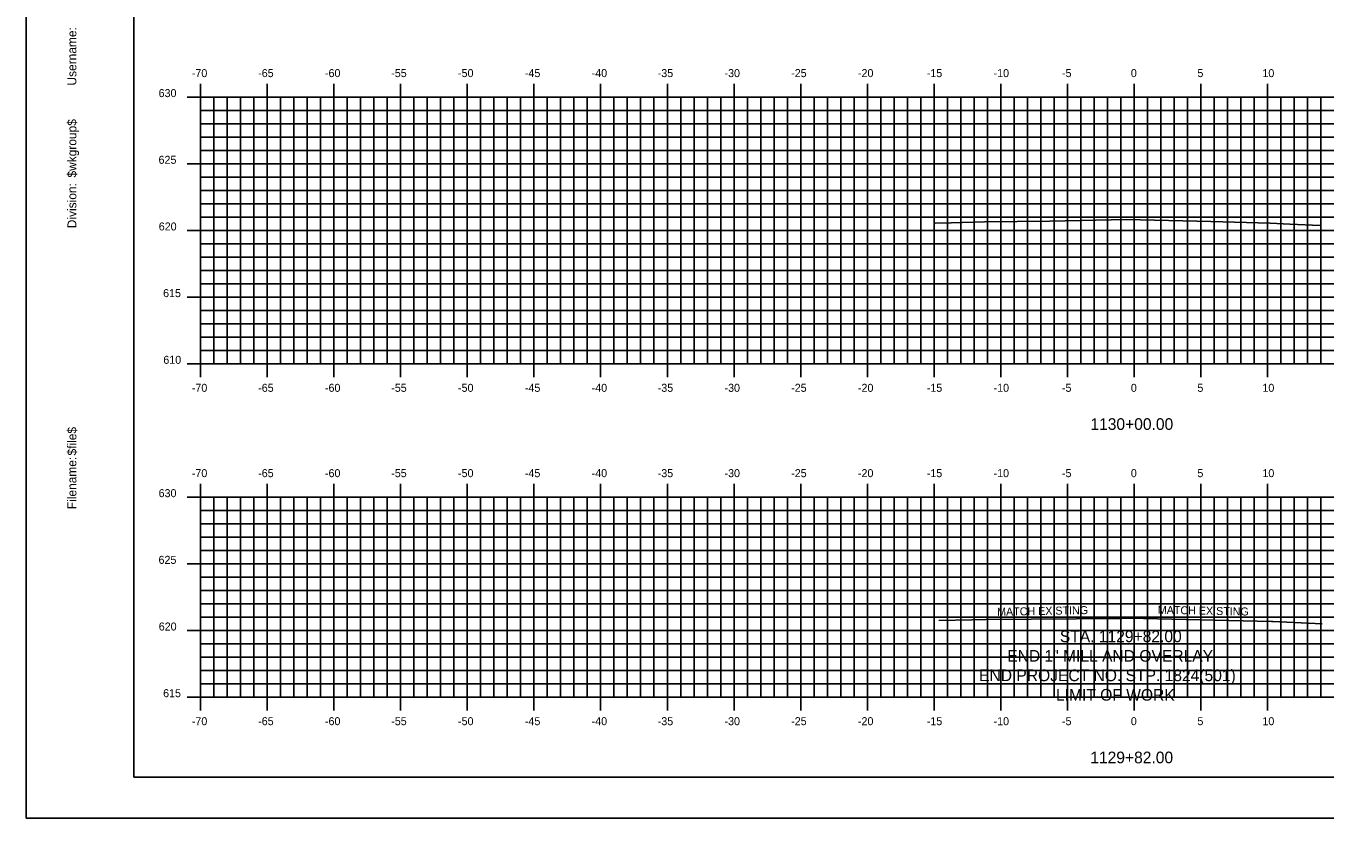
# Model space of a CAD drawing. Extents: x 1089609 to 1089779, y 779716 to 779826.
# Drawn here: x 1089609.1 to 1089706.6, y 779715.6 to 779775 of the extents above; entities that cross this region are included whole.
import ezdxf

# ---------------------------------------------------------------- set-up
doc = ezdxf.new("R2010")
doc.units = 0
for name, color, linetype in [('ANNOTATION', 7, 'Continuous'), ('BORDER', 7, 'Continuous'), ('H_V ANNOTATION', 7, 'Continuous'), ('MAJOR', 7, 'Continuous'), ('MINOR', 7, 'Continuous'), ('PLOT BOUNDARY', 7, 'Continuous'), ('S_Roadway_Centerline', 7, 'Continuous')]:
    doc.layers.add(name, color=color, linetype=linetype)

msp = doc.modelspace()

# ---------------------------------------------------------------- linework, layer by layer
at = {"layer": 'BORDER'}
msp.add_lwpolyline([(1089617.187, 779718.706), (1089777.187, 779718.706), (1089777.187, 779823.706), (1089617.187, 779823.706)], close=True, dxfattribs=at)
at = {"layer": 'MAJOR'}
for p, q in [((1089622.187, 779770.708), (1089622.187, 779769.706)), ((1089627.187, 779770.708), (1089627.187, 779769.706)), ((1089632.187, 779770.708), (1089632.187, 779769.706)), ((1089637.187, 779770.708), (1089637.187, 779769.706)), ((1089642.187, 779770.708), (1089642.187, 779769.706)), ((1089647.187, 779770.708), (1089647.187, 779769.706)), ((1089652.187, 779770.708), (1089652.187, 779769.706)), ((1089657.187, 779770.708), (1089657.187, 779769.706)), ((1089662.187, 779770.708), (1089662.187, 779769.706)), ((1089667.187, 779770.708), (1089667.187, 779769.706)), ((1089672.187, 779770.708), (1089672.187, 779769.706)), ((1089677.187, 779770.708), (1089677.187, 779769.706)), ((1089682.187, 779770.708), (1089682.187, 779769.706)), ((1089687.187, 779770.708), (1089687.187, 779769.706)), ((1089692.187, 779770.708), (1089692.187, 779769.706)), ((1089697.187, 779770.708), (1089697.187, 779769.706)), ((1089702.187, 779770.708), (1089702.187, 779769.706)), ((1089621.185, 779769.706), (1089622.187, 779769.706)), ((1089622.187, 779769.706), (1089762.187, 779769.706)), ((1089622.187, 779749.706), (1089622.187, 779769.706)), ((1089622.187, 779749.706), (1089622.187, 779769.706)), ((1089622.187, 779769.706), (1089762.187, 779769.706)), ((1089627.187, 779749.706), (1089627.187, 779769.706)), ((1089632.187, 779749.706), (1089632.187, 779769.706)), ((1089637.187, 779749.706), (1089637.187, 779769.706)), ((1089642.187, 779749.706), (1089642.187, 779769.706)), ((1089647.187, 779749.706), (1089647.187, 779769.706)), ((1089652.187, 779749.706), (1089652.187, 779769.706)), ((1089657.187, 779749.706), (1089657.187, 779769.706)), ((1089662.187, 779749.706), (1089662.187, 779769.706)), ((1089667.187, 779749.706), (1089667.187, 779769.706)), ((1089672.187, 779749.706), (1089672.187, 779769.706)), ((1089677.187, 779749.706), (1089677.187, 779769.706)), ((1089682.187, 779749.706), (1089682.187, 779769.706)), ((1089687.187, 779749.706), (1089687.187, 779769.706)), ((1089692.187, 779749.706), (1089692.187, 779769.706)), ((1089697.187, 779749.706), (1089697.187, 779769.706)), ((1089702.187, 779749.706), (1089702.187, 779769.706)), ((1089621.185, 779764.706), (1089622.187, 779764.706)), ((1089622.187, 779764.706), (1089762.187, 779764.706)), ((1089621.185, 779759.706), (1089622.187, 779759.706)), ((1089622.187, 779759.706), (1089762.187, 779759.706)), ((1089621.185, 779754.706), (1089622.187, 779754.706)), ((1089622.187, 779754.706), (1089762.187, 779754.706)), ((1089621.185, 779749.706), (1089622.187, 779749.706)), ((1089622.187, 779749.706), (1089762.187, 779749.706)), ((1089622.187, 779749.706), (1089762.187, 779749.706)), ((1089622.187, 779748.704), (1089622.187, 779749.706)), ((1089627.187, 779748.704), (1089627.187, 779749.706)), ((1089632.187, 779748.704), (1089632.187, 779749.706)), ((1089637.187, 779748.704), (1089637.187, 779749.706)), ((1089642.187, 779748.704), (1089642.187, 779749.706)), ((1089647.187, 779748.704), (1089647.187, 779749.706)), ((1089652.187, 779748.704), (1089652.187, 779749.706)), ((1089657.187, 779748.704), (1089657.187, 779749.706)), ((1089662.187, 779748.704), (1089662.187, 779749.706)), ((1089667.187, 779748.704), (1089667.187, 779749.706)), ((1089672.187, 779748.704), (1089672.187, 779749.706)), ((1089677.187, 779748.704), (1089677.187, 779749.706)), ((1089682.187, 779748.704), (1089682.187, 779749.706)), ((1089687.187, 779748.704), (1089687.187, 779749.706)), ((1089692.187, 779748.704), (1089692.187, 779749.706)), ((1089697.187, 779748.704), (1089697.187, 779749.706)), ((1089702.187, 779748.704), (1089702.187, 779749.706)), ((1089622.187, 779740.708), (1089622.187, 779739.706)), ((1089627.187, 779740.708), (1089627.187, 779739.706)), ((1089632.187, 779740.708), (1089632.187, 779739.706)), ((1089637.187, 779740.708), (1089637.187, 779739.706)), ((1089642.187, 779740.708), (1089642.187, 779739.706)), ((1089647.187, 779740.708), (1089647.187, 779739.706)), ((1089652.187, 779740.708), (1089652.187, 779739.706)), ((1089657.187, 779740.708), (1089657.187, 779739.706)), ((1089662.187, 779740.708), (1089662.187, 779739.706)), ((1089667.187, 779740.708), (1089667.187, 779739.706)), ((1089672.187, 779740.708), (1089672.187, 779739.706)), ((1089677.187, 779740.708), (1089677.187, 779739.706)), ((1089682.187, 779740.708), (1089682.187, 779739.706)), ((1089687.187, 779740.708), (1089687.187, 779739.706)), ((1089692.187, 779740.708), (1089692.187, 779739.706)), ((1089697.187, 779740.708), (1089697.187, 779739.706)), ((1089702.187, 779740.708), (1089702.187, 779739.706)), ((1089621.185, 779739.706), (1089622.187, 779739.706)), ((1089622.187, 779739.706), (1089762.187, 779739.706)), ((1089622.187, 779724.706), (1089622.187, 779739.706)), ((1089622.187, 779724.706), (1089622.187, 779739.706)), ((1089622.187, 779739.706), (1089762.187, 779739.706)), ((1089627.187, 779724.706), (1089627.187, 779739.706)), ((1089632.187, 779724.706), (1089632.187, 779739.706)), ((1089637.187, 779724.706), (1089637.187, 779739.706)), ((1089642.187, 779724.706), (1089642.187, 779739.706)), ((1089647.187, 779724.706), (1089647.187, 779739.706)), ((1089652.187, 779724.706), (1089652.187, 779739.706)), ((1089657.187, 779724.706), (1089657.187, 779739.706)), ((1089662.187, 779724.706), (1089662.187, 779739.706)), ((1089667.187, 779724.706), (1089667.187, 779739.706)), ((1089672.187, 779724.706), (1089672.187, 779739.706)), ((1089677.187, 779724.706), (1089677.187, 779739.706)), ((1089682.187, 779724.706), (1089682.187, 779739.706)), ((1089687.187, 779724.706), (1089687.187, 779739.706)), ((1089692.187, 779724.706), (1089692.187, 779739.706)), ((1089697.187, 779724.706), (1089697.187, 779739.706)), ((1089702.187, 779724.706), (1089702.187, 779739.706)), ((1089621.185, 779734.706), (1089622.187, 779734.706)), ((1089622.187, 779734.706), (1089762.187, 779734.706)), ((1089621.185, 779729.706), (1089622.187, 779729.706)), ((1089622.187, 779729.706), (1089762.187, 779729.706)), ((1089621.185, 779724.706), (1089622.187, 779724.706)), ((1089622.187, 779724.706), (1089762.187, 779724.706)), ((1089622.187, 779724.706), (1089762.187, 779724.706)), ((1089622.187, 779723.704), (1089622.187, 779724.706)), ((1089627.187, 779723.704), (1089627.187, 779724.706)), ((1089632.187, 779723.704), (1089632.187, 779724.706)), ((1089637.187, 779723.704), (1089637.187, 779724.706)), ((1089642.187, 779723.704), (1089642.187, 779724.706)), ((1089647.187, 779723.704), (1089647.187, 779724.706)), ((1089652.187, 779723.704), (1089652.187, 779724.706)), ((1089657.187, 779723.704), (1089657.187, 779724.706)), ((1089662.187, 779723.704), (1089662.187, 779724.706)), ((1089667.187, 779723.704), (1089667.187, 779724.706)), ((1089672.187, 779723.704), (1089672.187, 779724.706)), ((1089677.187, 779723.704), (1089677.187, 779724.706)), ((1089682.187, 779723.704), (1089682.187, 779724.706)), ((1089687.187, 779723.704), (1089687.187, 779724.706)), ((1089692.187, 779723.704), (1089692.187, 779724.706)), ((1089697.187, 779723.704), (1089697.187, 779724.706)), ((1089702.187, 779723.704), (1089702.187, 779724.706))]:
    msp.add_line(p, q, dxfattribs=at)
at = {"layer": 'MINOR'}
for p, q in [((1089623.187, 779749.706), (1089623.187, 779769.706)), ((1089624.187, 779749.706), (1089624.187, 779769.706)), ((1089625.187, 779749.706), (1089625.187, 779769.706)), ((1089626.187, 779749.706), (1089626.187, 779769.706)), ((1089628.187, 779749.706), (1089628.187, 779769.706)), ((1089629.187, 779749.706), (1089629.187, 779769.706)), ((1089630.187, 779749.706), (1089630.187, 779769.706)), ((1089631.187, 779749.706), (1089631.187, 779769.706)), ((1089633.187, 779749.706), (1089633.187, 779769.706)), ((1089634.187, 779749.706), (1089634.187, 779769.706)), ((1089635.187, 779749.706), (1089635.187, 779769.706)), ((1089636.187, 779749.706), (1089636.187, 779769.706)), ((1089638.187, 779749.706), (1089638.187, 779769.706)), ((1089639.187, 779749.706), (1089639.187, 779769.706)), ((1089640.187, 779749.706), (1089640.187, 779769.706)), ((1089641.187, 779749.706), (1089641.187, 779769.706)), ((1089643.187, 779749.706), (1089643.187, 779769.706)), ((1089644.187, 779749.706), (1089644.187, 779769.706)), ((1089645.187, 779749.706), (1089645.187, 779769.706)), ((1089646.187, 779749.706), (1089646.187, 779769.706)), ((1089648.187, 779749.706), (1089648.187, 779769.706)), ((1089649.187, 779749.706), (1089649.187, 779769.706)), ((1089650.187, 779749.706), (1089650.187, 779769.706)), ((1089651.187, 779749.706), (1089651.187, 779769.706)), ((1089653.187, 779749.706), (1089653.187, 779769.706)), ((1089654.187, 779749.706), (1089654.187, 779769.706)), ((1089655.187, 779749.706), (1089655.187, 779769.706)), ((1089656.187, 779749.706), (1089656.187, 779769.706)), ((1089658.187, 779749.706), (1089658.187, 779769.706)), ((1089659.187, 779749.706), (1089659.187, 779769.706)), ((1089660.187, 779749.706), (1089660.187, 779769.706)), ((1089661.187, 779749.706), (1089661.187, 779769.706)), ((1089663.187, 779749.706), (1089663.187, 779769.706)), ((1089664.187, 779749.706), (1089664.187, 779769.706)), ((1089665.187, 779749.706), (1089665.187, 779769.706)), ((1089666.187, 779749.706), (1089666.187, 779769.706)), ((1089668.187, 779749.706), (1089668.187, 779769.706)), ((1089669.187, 779749.706), (1089669.187, 779769.706)), ((1089670.187, 779749.706), (1089670.187, 779769.706)), ((1089671.187, 779749.706), (1089671.187, 779769.706)), ((1089673.187, 779749.706), (1089673.187, 779769.706)), ((1089674.187, 779749.706), (1089674.187, 779769.706)), ((1089675.187, 779749.706), (1089675.187, 779769.706)), ((1089676.187, 779749.706), (1089676.187, 779769.706)), ((1089678.187, 779749.706), (1089678.187, 779769.706)), ((1089679.187, 779749.706), (1089679.187, 779769.706)), ((1089680.187, 779749.706), (1089680.187, 779769.706)), ((1089681.187, 779749.706), (1089681.187, 779769.706)), ((1089683.187, 779749.706), (1089683.187, 779769.706)), ((1089684.187, 779749.706), (1089684.187, 779769.706)), ((1089685.187, 779749.706), (1089685.187, 779769.706)), ((1089686.187, 779749.706), (1089686.187, 779769.706)), ((1089688.187, 779749.706), (1089688.187, 779769.706)), ((1089689.187, 779749.706), (1089689.187, 779769.706)), ((1089690.187, 779749.706), (1089690.187, 779769.706)), ((1089691.187, 779749.706), (1089691.187, 779769.706)), ((1089693.187, 779749.706), (1089693.187, 779769.706)), ((1089694.187, 779749.706), (1089694.187, 779769.706)), ((1089695.187, 779749.706), (1089695.187, 779769.706)), ((1089696.187, 779749.706), (1089696.187, 779769.706)), ((1089698.187, 779749.706), (1089698.187, 779769.706)), ((1089699.187, 779749.706), (1089699.187, 779769.706)), ((1089700.187, 779749.706), (1089700.187, 779769.706)), ((1089701.187, 779749.706), (1089701.187, 779769.706)), ((1089703.187, 779749.706), (1089703.187, 779769.706)), ((1089704.187, 779749.706), (1089704.187, 779769.706)), ((1089705.187, 779749.706), (1089705.187, 779769.706)), ((1089706.187, 779749.706), (1089706.187, 779769.706)), ((1089622.187, 779768.706), (1089762.187, 779768.706)), ((1089622.187, 779768.706), (1089623.189, 779768.706)), ((1089622.187, 779767.706), (1089762.187, 779767.706)), ((1089622.187, 779767.706), (1089623.189, 779767.706)), ((1089622.187, 779766.706), (1089762.187, 779766.706)), ((1089622.187, 779766.706), (1089623.189, 779766.706)), ((1089622.187, 779765.706), (1089762.187, 779765.706)), ((1089622.187, 779765.706), (1089623.189, 779765.706)), ((1089622.187, 779763.706), (1089762.187, 779763.706)), ((1089622.187, 779763.706), (1089623.189, 779763.706)), ((1089622.187, 779762.706), (1089762.187, 779762.706)), ((1089622.187, 779762.706), (1089623.189, 779762.706)), ((1089622.187, 779761.706), (1089762.187, 779761.706)), ((1089622.187, 779761.706), (1089623.189, 779761.706)), ((1089622.187, 779760.706), (1089762.187, 779760.706)), ((1089622.187, 779760.706), (1089623.189, 779760.706)), ((1089622.187, 779758.706), (1089762.187, 779758.706)), ((1089622.187, 779758.706), (1089623.189, 779758.706)), ((1089622.187, 779757.706), (1089762.187, 779757.706)), ((1089622.187, 779757.706), (1089623.189, 779757.706)), ((1089622.187, 779756.706), (1089762.187, 779756.706)), ((1089622.187, 779756.706), (1089623.189, 779756.706)), ((1089622.187, 779755.706), (1089762.187, 779755.706)), ((1089622.187, 779755.706), (1089623.189, 779755.706)), ((1089622.187, 779753.706), (1089762.187, 779753.706)), ((1089622.187, 779753.706), (1089623.189, 779753.706)), ((1089622.187, 779752.706), (1089762.187, 779752.706)), ((1089622.187, 779752.706), (1089623.189, 779752.706)), ((1089622.187, 779751.706), (1089762.187, 779751.706)), ((1089622.187, 779751.706), (1089623.189, 779751.706)), ((1089622.187, 779750.706), (1089762.187, 779750.706)), ((1089622.187, 779750.706), (1089623.189, 779750.706)), ((1089623.187, 779724.706), (1089623.187, 779739.706)), ((1089624.187, 779724.706), (1089624.187, 779739.706)), ((1089625.187, 779724.706), (1089625.187, 779739.706)), ((1089626.187, 779724.706), (1089626.187, 779739.706)), ((1089628.187, 779724.706), (1089628.187, 779739.706)), ((1089629.187, 779724.706), (1089629.187, 779739.706)), ((1089630.187, 779724.706), (1089630.187, 779739.706)), ((1089631.187, 779724.706), (1089631.187, 779739.706)), ((1089633.187, 779724.706), (1089633.187, 779739.706)), ((1089634.187, 779724.706), (1089634.187, 779739.706)), ((1089635.187, 779724.706), (1089635.187, 779739.706)), ((1089636.187, 779724.706), (1089636.187, 779739.706)), ((1089638.187, 779724.706), (1089638.187, 779739.706)), ((1089639.187, 779724.706), (1089639.187, 779739.706)), ((1089640.187, 779724.706), (1089640.187, 779739.706)), ((1089641.187, 779724.706), (1089641.187, 779739.706)), ((1089643.187, 779724.706), (1089643.187, 779739.706)), ((1089644.187, 779724.706), (1089644.187, 779739.706)), ((1089645.187, 779724.706), (1089645.187, 779739.706)), ((1089646.187, 779724.706), (1089646.187, 779739.706)), ((1089648.187, 779724.706), (1089648.187, 779739.706)), ((1089649.187, 779724.706), (1089649.187, 779739.706)), ((1089650.187, 779724.706), (1089650.187, 779739.706)), ((1089651.187, 779724.706), (1089651.187, 779739.706)), ((1089653.187, 779724.706), (1089653.187, 779739.706)), ((1089654.187, 779724.706), (1089654.187, 779739.706)), ((1089655.187, 779724.706), (1089655.187, 779739.706)), ((1089656.187, 779724.706), (1089656.187, 779739.706)), ((1089658.187, 779724.706), (1089658.187, 779739.706)), ((1089659.187, 779724.706), (1089659.187, 779739.706)), ((1089660.187, 779724.706), (1089660.187, 779739.706)), ((1089661.187, 779724.706), (1089661.187, 779739.706)), ((1089663.187, 779724.706), (1089663.187, 779739.706)), ((1089664.187, 779724.706), (1089664.187, 779739.706)), ((1089665.187, 779724.706), (1089665.187, 779739.706)), ((1089666.187, 779724.706), (1089666.187, 779739.706)), ((1089668.187, 779724.706), (1089668.187, 779739.706)), ((1089669.187, 779724.706), (1089669.187, 779739.706)), ((1089670.187, 779724.706), (1089670.187, 779739.706)), ((1089671.187, 779724.706), (1089671.187, 779739.706)), ((1089673.187, 779724.706), (1089673.187, 779739.706)), ((1089674.187, 779724.706), (1089674.187, 779739.706)), ((1089675.187, 779724.706), (1089675.187, 779739.706)), ((1089676.187, 779724.706), (1089676.187, 779739.706)), ((1089678.187, 779724.706), (1089678.187, 779739.706)), ((1089679.187, 779724.706), (1089679.187, 779739.706)), ((1089680.187, 779724.706), (1089680.187, 779739.706)), ((1089681.187, 779724.706), (1089681.187, 779739.706)), ((1089683.187, 779724.706), (1089683.187, 779739.706)), ((1089684.187, 779724.706), (1089684.187, 779739.706)), ((1089685.187, 779724.706), (1089685.187, 779739.706)), ((1089686.187, 779724.706), (1089686.187, 779739.706)), ((1089688.187, 779724.706), (1089688.187, 779739.706)), ((1089689.187, 779724.706), (1089689.187, 779739.706)), ((1089690.187, 779724.706), (1089690.187, 779739.706)), ((1089691.187, 779724.706), (1089691.187, 779739.706)), ((1089693.187, 779724.706), (1089693.187, 779739.706)), ((1089694.187, 779724.706), (1089694.187, 779739.706)), ((1089695.187, 779724.706), (1089695.187, 779739.706)), ((1089696.187, 779724.706), (1089696.187, 779739.706)), ((1089698.187, 779724.706), (1089698.187, 779739.706)), ((1089699.187, 779724.706), (1089699.187, 779739.706)), ((1089700.187, 779724.706), (1089700.187, 779739.706)), ((1089701.187, 779724.706), (1089701.187, 779739.706)), ((1089703.187, 779724.706), (1089703.187, 779739.706)), ((1089704.187, 779724.706), (1089704.187, 779739.706)), ((1089705.187, 779724.706), (1089705.187, 779739.706)), ((1089706.187, 779724.706), (1089706.187, 779739.706)), ((1089622.187, 779738.706), (1089762.187, 779738.706)), ((1089622.187, 779738.706), (1089623.189, 779738.706)), ((1089622.187, 779737.706), (1089762.187, 779737.706)), ((1089622.187, 779737.706), (1089623.189, 779737.706)), ((1089622.187, 779736.706), (1089762.187, 779736.706)), ((1089622.187, 779736.706), (1089623.189, 779736.706)), ((1089622.187, 779735.706), (1089762.187, 779735.706)), ((1089622.187, 779735.706), (1089623.189, 779735.706)), ((1089622.187, 779733.706), (1089762.187, 779733.706)), ((1089622.187, 779733.706), (1089623.189, 779733.706)), ((1089622.187, 779732.706), (1089762.187, 779732.706)), ((1089622.187, 779732.706), (1089623.189, 779732.706)), ((1089622.187, 779731.706), (1089762.187, 779731.706)), ((1089622.187, 779731.706), (1089623.189, 779731.706)), ((1089622.187, 779730.706), (1089762.187, 779730.706)), ((1089622.187, 779730.706), (1089623.189, 779730.706)), ((1089622.187, 779728.706), (1089762.187, 779728.706)), ((1089622.187, 779728.706), (1089623.189, 779728.706)), ((1089622.187, 779727.706), (1089762.187, 779727.706)), ((1089622.187, 779727.706), (1089623.189, 779727.706)), ((1089622.187, 779726.706), (1089762.187, 779726.706)), ((1089622.187, 779726.706), (1089623.189, 779726.706)), ((1089622.187, 779725.706), (1089762.187, 779725.706)), ((1089622.187, 779725.706), (1089623.189, 779725.706))]:
    msp.add_line(p, q, dxfattribs=at)
at = {"layer": 'PLOT BOUNDARY'}
msp.add_lwpolyline([(1089609.094, 779715.646), (1089779.094, 779715.646), (1089779.094, 779825.646), (1089609.094, 779825.646)], close=True, dxfattribs=at)
at = {"layer": 'S_Roadway_Centerline'}
for points in [[(1089677.284, 779760.26), (1089678.473, 779760.285), (1089680.974, 779760.357), (1089685.858, 779760.398), (1089691.618, 779760.52), (1089697.94, 779760.373), (1089702.401, 779760.256), (1089703.866, 779760.182), (1089706.13, 779760.076)], [(1089677.549, 779730.451), (1089680.033, 779730.502), (1089681.075, 779730.532), (1089691.282, 779730.619), (1089691.826, 779730.63), (1089702.491, 779730.383), (1089702.561, 779730.382), (1089702.584, 779730.38), (1089706.294, 779730.207)]]:
    msp.add_lwpolyline(points, dxfattribs=at)

# ---------------------------------------------------------------- texts
at = {"layer": 'ANNOTATION'}
for rotation, p in [(1.14576, (1089681.924, 779730.805)), (358.85424, (1089693.964, 779730.964))]:
    msp.add_text('MATCH EXISTING', height=0.6, rotation=rotation, dxfattribs=at).set_placement(p)
for s, p in [('STA. 1129+82.00', (1089686.621, 779728.831)), ('END 1" MILL AND OVERLAY', (1089682.675, 779727.369)), ('END PROJECT NO. STP. 1824(501)', (1089680.566, 779725.908)), ('LIMIT OF WORK', (1089686.332, 779724.447))]:
    msp.add_text(s, height=0.875, dxfattribs=at).set_placement(p)
at = {"layer": 'BORDER'}
for s, p in [('Username:', (1089612.872, 779770.573)), ('$wkgroup$', (1089612.872, 779763.675)), ('Division:', (1089612.872, 779759.872)), ('$file$', (1089612.872, 779742.831)), ('Filename:', (1089612.872, 779738.804))]:
    msp.add_text(s, height=0.6696, rotation=90, dxfattribs=at).set_placement(p)
at = {"layer": 'H_V ANNOTATION'}
for s, height, p in [('-70', 0.6, (1089621.529, 779771.206)), ('-65', 0.6, (1089626.505, 779771.206)), ('-60', 0.6, (1089631.513, 779771.206)), ('-55', 0.6, (1089636.483, 779771.206)), ('-50', 0.6, (1089641.491, 779771.206)), ('-45', 0.6, (1089646.505, 779771.206)), ('-40', 0.6, (1089651.513, 779771.206)), ('-35', 0.6, (1089656.467, 779771.206)), ('-30', 0.6, (1089661.475, 779771.206)), ('-25', 0.6, (1089666.473, 779771.206)), ('-20', 0.6, (1089671.481, 779771.206)), ('-15', 0.6, (1089676.644, 779771.206)), ('-10', 0.6, (1089681.652, 779771.206)), ('-5', 0.6, (1089686.778, 779771.206)), ('0', 0.6, (1089691.946, 779771.206)), ('5', 0.6, (1089696.938, 779771.206)), ('10', 0.6, (1089701.812, 779771.206)), ('630', 0.6, (1089619.039, 779769.706)), ('625', 0.6, (1089619.033, 779764.706)), ('620', 0.6, (1089619.049, 779759.706)), ('615', 0.6, (1089619.376, 779754.706)), ('610', 0.6, (1089619.392, 779749.706)), ('-70', 0.6, (1089621.529, 779747.606)), ('-65', 0.6, (1089626.505, 779747.606)), ('-60', 0.6, (1089631.513, 779747.606)), ('-55', 0.6, (1089636.483, 779747.606)), ('-50', 0.6, (1089641.491, 779747.606)), ('-45', 0.6, (1089646.505, 779747.606)), ('-40', 0.6, (1089651.513, 779747.606)), ('-35', 0.6, (1089656.467, 779747.606)), ('-30', 0.6, (1089661.475, 779747.606)), ('-25', 0.6, (1089666.473, 779747.606)), ('-20', 0.6, (1089671.481, 779747.606)), ('-15', 0.6, (1089676.644, 779747.606)), ('-10', 0.6, (1089681.652, 779747.606)), ('-5', 0.6, (1089686.778, 779747.606)), ('0', 0.6, (1089691.946, 779747.606)), ('5', 0.6, (1089696.938, 779747.606)), ('10', 0.6, (1089701.812, 779747.606)), ('1130+00.00', 0.875, (1089688.91, 779744.749)), ('-70', 0.6, (1089621.529, 779741.206)), ('-65', 0.6, (1089626.505, 779741.206)), ('-60', 0.6, (1089631.513, 779741.206)), ('-55', 0.6, (1089636.483, 779741.206)), ('-50', 0.6, (1089641.491, 779741.206)), ('-45', 0.6, (1089646.505, 779741.206)), ('-40', 0.6, (1089651.513, 779741.206)), ('-35', 0.6, (1089656.467, 779741.206)), ('-30', 0.6, (1089661.475, 779741.206)), ('-25', 0.6, (1089666.473, 779741.206)), ('-20', 0.6, (1089671.481, 779741.206)), ('-15', 0.6, (1089676.644, 779741.206)), ('-10', 0.6, (1089681.652, 779741.206)), ('-5', 0.6, (1089686.778, 779741.206)), ('0', 0.6, (1089691.946, 779741.206)), ('5', 0.6, (1089696.938, 779741.206)), ('10', 0.6, (1089701.812, 779741.206)), ('630', 0.6, (1089619.039, 779739.706)), ('625', 0.6, (1089619.033, 779734.706)), ('620', 0.6, (1089619.049, 779729.706)), ('615', 0.6, (1089619.376, 779724.706)), ('-70', 0.6, (1089621.529, 779722.606)), ('-65', 0.6, (1089626.505, 779722.606)), ('-60', 0.6, (1089631.513, 779722.606)), ('-55', 0.6, (1089636.483, 779722.606)), ('-50', 0.6, (1089641.491, 779722.606)), ('-45', 0.6, (1089646.505, 779722.606)), ('-40', 0.6, (1089651.513, 779722.606)), ('-35', 0.6, (1089656.467, 779722.606)), ('-30', 0.6, (1089661.475, 779722.606)), ('-25', 0.6, (1089666.473, 779722.606)), ('-20', 0.6, (1089671.481, 779722.606)), ('-15', 0.6, (1089676.644, 779722.606)), ('-10', 0.6, (1089681.652, 779722.606)), ('-5', 0.6, (1089686.778, 779722.606)), ('0', 0.6, (1089691.946, 779722.606)), ('5', 0.6, (1089696.938, 779722.606)), ('10', 0.6, (1089701.812, 779722.606)), ('1129+82.00', 0.875, (1089688.902, 779719.749))]:
    msp.add_text(s, height=height, dxfattribs=at).set_placement(p)
at = {"layer": 'MAJOR'}
for p in [(1089622.183, 779749.706), (1089622.183, 779724.706)]:
    msp.add_text('-', height=0.006, dxfattribs=at).set_placement(p)
at = {"layer": 'S_Roadway_Centerline'}
for s, p in [('C', (1089691.821, 779730.63)), ('L', (1089691.826, 779730.623))]:
    msp.add_text(s, height=0.0146, dxfattribs=at).set_placement(p)

doc.saveas('drawing.dxf')
